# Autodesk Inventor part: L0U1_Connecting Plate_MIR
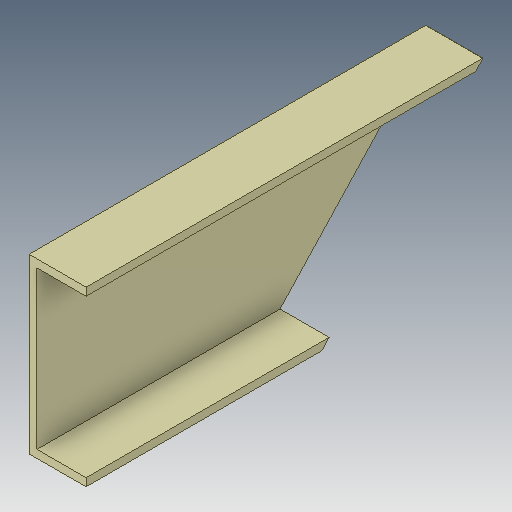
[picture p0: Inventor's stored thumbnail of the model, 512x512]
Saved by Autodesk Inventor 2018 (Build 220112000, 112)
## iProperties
Created: 2018-02
Part Number: L0U1_Connecting Plate_MIR
Material: Steel, Mild
Document SubType Name: Modeling
Designer: STK
Density: 7.85 g/cm^3
Appearance: Semi-Polished
Author: STK
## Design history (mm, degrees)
derived "L0U1_Connecting Plate.ipt"
  sketch "Sketch1"
    geometry: L1 (-12.7, 127)-(-12.7, -127) reference; L2 (0, -139.7)-(0, 139.7) reference; L3 (0, -139.7)-(-92.075, -139.7) reference; L4 (-92.075, -139.7)-(-92.075, -127) reference; L5 (-92.075, -127)-(-12.7, -127) reference; L6 (0, 139.7)-(-92.075, 139.7) reference; L7 (-92.075, 139.7)-(-92.075, 127) reference; L8 (-92.075, 127)-(-12.7, 127) reference; L9 (0, 0)-(-92.075, 0) reference
  sketch "Sketch2"
    geometry: L1 (260.35, 0)-(0.379, 278.525) reference; L2 (0, 0)-(641.35, 0) reference; L3 (0, 279.4)-(0, 0) reference; L4 (0, 0)-(0, 278.931) reference; L5 (260.35, 0)-(0, 278.931) reference; L6 (0, 0)-(260.35, 0) reference; 1 further point
feature "Solid1::L0U1_Connecting Plate.ipt" dims "d0" = 10
tag "TaggingFeature1"
body "Solid1"
